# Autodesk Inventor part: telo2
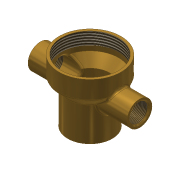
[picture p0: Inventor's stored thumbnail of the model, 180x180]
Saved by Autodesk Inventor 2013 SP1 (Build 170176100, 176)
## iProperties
Created: 2013-01
Part Number: telo2
Material: Mosaz, měkká žlutá
Document SubType Name: Modeling
Designer: pospisil
Density: 8.47 g/cm^3
Mass: 150.478 g
Surface Area: 170.057 cm^2
Volume: 17.766 cm^3
Author: pospisil
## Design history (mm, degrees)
sketch "Náčrt1"
  geometry: L1 (0, 0)-(0, 50); L2 (25, 50)-(25, 35); L3 (25, 35)-(17.929, 27.929); L4 (17.929, 27.929)-(17.929, 0); L5 (17.929, 0)-(15.929, 0); L6 (15.929, 0)-(15.929, 29); L7 (15.929, 29)-(23, 36.071); L8 (23, 36.071)-(23, 50); L9 (23, 50)-(25, 50)
  constraints: 18 end point, 4 parallel, 1 perpendicular, 1 vertical
  dimensions: "d0" = 50 distance of L1.start L1.end; "d1" = 25 distance of L1.end L2.start; "d2" = 15 distance of L2.start L2.end; "d3" = 10 distance of L2.end L3.end; "d4" = 135 deg angle of L2 L3; "d5" = 2 distance of L4.end L5.end; "d6" = 29 distance of L5.end L6.end; "d7" = 10 distance of L6.end L7.end
revolve "Rotace1" sketch "Náčrt1" stored, may be unused: angle "d8" = 90 deg
sketch "Náčrt2"
  geometry: C1 r 7.5 at (0, 28.705); C2 r 10 at (0, 28.705); 1 further point
  constraints: 2 centre point, 1 coincident
  dimensions: "d9" = 15 diameter of C1; "d10" = 20 diameter of C2
extrude "Vysunutí1" join sketch "Náčrt2" stored distance "d11" = 80; taper "d12" = 0 deg
feature "Odstranit plochu1"
sketch "Náčrt3"
  geometry: C1 r 7.5 at (0, 0) reference; 1 further point
extrude "Vysunutí2" cut sketch "Náčrt3" distance "d13" = 80; taper "d14" = 0 deg
fillet "Zaoblení1" dims "d15" = 2
chamfer "Zkosení1" distance "d16" = 1; stored, may be unused: second distance "d17" = 2, angle "d18" = 45 deg
feature "Závit1" dims "d19" = 15, "d20" = 0
feature "Závit2" dims "d21" = 10, "d22" = 0
feature "Závit3" dims "d23" = 10, "d24" = 0
feature "Závit4" dims "d25" = 10, "d26" = 0
node "Těleso1"
